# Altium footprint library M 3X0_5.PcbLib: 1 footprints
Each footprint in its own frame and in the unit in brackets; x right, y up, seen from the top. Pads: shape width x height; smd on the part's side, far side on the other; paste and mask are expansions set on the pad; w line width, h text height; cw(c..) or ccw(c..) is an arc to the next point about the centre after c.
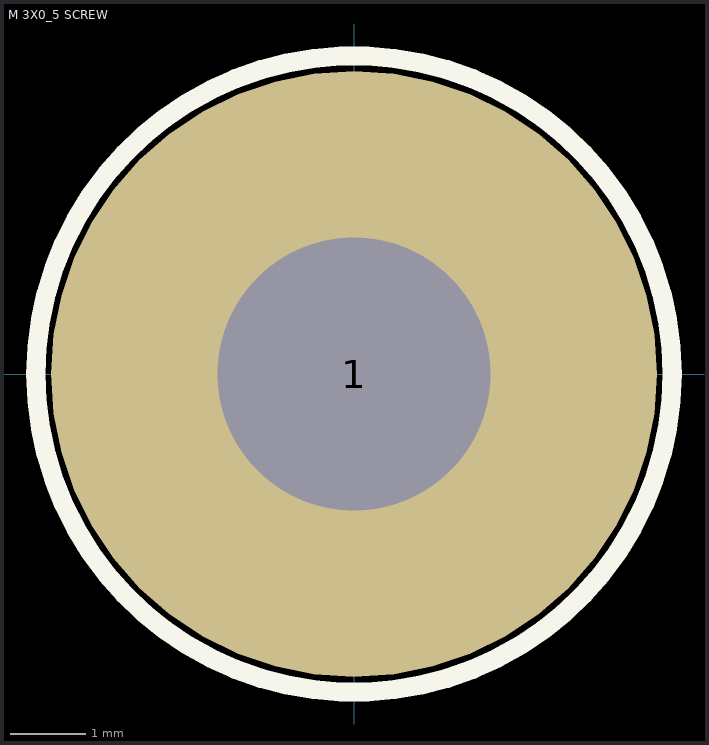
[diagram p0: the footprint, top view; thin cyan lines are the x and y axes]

## M 3X0_5 SCREW [mm] "M 3X0.5 SCREW"
height 2.4
pads (1):
  round 8 hole 3.6: 1(0,0)
Top Overlay:
  circle w0.254: c0,0 r4.2
M5 Assembly Top:
  text ".Designator" at -0.1,-0.1 h1.02
3D body: height 2.5, standoff 0, extent -4.356,-4.3 4.3,4.3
